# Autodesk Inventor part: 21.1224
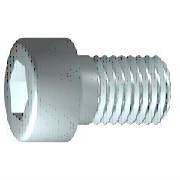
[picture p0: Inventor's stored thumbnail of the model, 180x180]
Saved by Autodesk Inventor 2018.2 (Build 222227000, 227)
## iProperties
Created: 2006-02
Part Number: 21.1224
Material: Steel, Mild
Description: M5 X 25 SHCS
Document SubType Name: Modeling
Standard: DIN 7984
Designer: Andy Moles
Standards Organization: DIN
Language: en-US
Size Designation: M5 x 25
Categories: <MemberInstance><Categories><Category DisplayName="Fasteners" InternalName="e4da775c-781d-43d5-af7c-5136215cf5a6" Mnemonic="FSTN"><Category DisplayName="Bolts"
Density: 7.85 g/cm^3
Mass: 5.19842 g
Surface Area: 6.19161 cm^2
Volume: 0.662219 cm^3
Appearance: Zinc
Author: Andy Moles
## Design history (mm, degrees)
sketch "Sketch1"
  geometry: L1 (0.2, 0)-(25, 0); L2 (25, 0)-(25, 2.5); L3 (25, 2.5)-(2.4, 2.5); L4 (2.4, 2.5)-(1.909, 2.5); L5 (1.909, 2.5)-(0, 2.5); L6 (0, 2.5)-(0, 4.25); L7 (0, 4.25)-(-3.5, 4.25); L8 (-3.5, 4.25)-(-3.5, 1.732); L9 (-3.5, 1.732)-(-0.8, 1.732); L10 (-0.8, 1.732)-(0.2, 0); L11 (-6.35, 0)-(33.55, 0) reference; L12 (0, -0.425)-(0, 5.525) reference; L13 (2.4, 2.5)-(0, 2.5)
  constraints: 22 end point, 6 parallel, 2 collinear, 2 perpendicular, 1 horizontal, 1 point on line
  dimensions: "d1" = 22.6 distance from line of L3.end L2 (= GEL); "d2" = 0.49086 distance of L4.end L3.end (computed from GAL); "d3" = 3.5 distance between parallel lines of L8 L6 (= KOH); "d4" = 2.7 distance of L8.end L9.end (= INTI); "d5" = 60 deg angle of L10 L1; "d6" = 5 diameter of L3 L1 (= GD); "d7" = 5 diameter of L5 L1 (= BDM); "d8" = 3.4641 diameter of L9 L1 (= 1.1547 x SW); "d9" = 8.5 diameter of L7 L1 (= KOD); "d26" = 25 distance between parallel lines of L12 L2 (= NLG)
revolve "Body" sketch "Sketch1" stored, may be unused: angle "d10" = 90 deg
sketch "Sketch2"
  geometry: L1 (0, -5.1)-(0, 6.8) reference; L2 (-5.1, 0)-(6.8, 0) reference; L3 (1.732, 0)-(0.866, -1.5); L4 (0.866, -1.5)-(-0.866, -1.5); L5 (-0.866, -1.5)-(-1.732, 0); L6 (-1.732, 0)-(-0.866, 1.5); L7 (-0.866, 1.5)-(0.866, 1.5); L8 (0.866, 1.5)-(1.732, 0); 2 further points
  constraints: 12 end point, 1 coincident, 1 horizontal alignment, 1 point on line, 12 other
extrude "Slot" join sketch "Sketch2" stored distance "d11" = 10; taper "d12" = 0 deg
workplane "Work Plane1"
body "Solid1"
fillet "Fillet1" dims "d17" = 0.5 (= RR)
feature "Thread" dims "d13" = 25, "d14" = 0
chamfer "Chamfer1" distance "d15" = 0.49076 (= -0.5 x SPD + 0.5 x GD); stored, may be unused: second distance "d16" = 0.49076 (= GUL), angle "d27" = 45 deg
other parameters: "GD" = 5 (= NND) [user parameter; used in 2 equation terms], "NLG" = 25 [user parameter; used in 1 equation term], "GEL" = 22.6 [user parameter; used in 1 equation term], "KOD" = 8.5 [user parameter; used in 1 equation term], "KOH" = 3.5 [user parameter; used in 1 equation term], "INTI" = 2.7 [user parameter; used in 1 equation term], "GAL" = 0.49076 (= 0.61345 x PTC) [user parameter; used in 1 equation term], "GUL" = 0.49076 (= 0.61345 x PTC) [user parameter; used in 1 equation term], "BDM" = 5 (= NND) [user parameter; used in 1 equation term], "SW" = 3 [user parameter; used in 2 equation terms], "RR" = 0.5 [user parameter; used in 1 equation term], "SPD" = 4.01848 (= NND - 1.2269 x PTC) [user parameter; used in 1 equation term], "d19" = 0, "d28" = 0, "d29" = 0, "TOA" = 30 deg [user parameter], "GD1" = 4.01848 (= THREADDIA - 1.2269 x PTC) [user parameter], "THREADDIA" = 5 [user parameter; used in 1 equation term], "FAWI" = 45 deg [user parameter], "ANG" = 120 deg [user parameter], "TPU" = 12.5 (computed from PTC) [user parameter], "PTC" = 0.8 [user parameter; used in 5 equation terms], "NND" = 5 [user parameter; used in 3 equation terms], "E0" = 3.465 (= 1.155 x SW) [user parameter]
